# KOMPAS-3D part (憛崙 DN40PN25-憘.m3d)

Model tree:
1. Объединить компоненты:1  (labels: СЕНС DN40PN25)
2. Эскиз:1
3. Операция выдавливания:1
     Расстояние 1 = 14
4. Фаска:1
     Угол = 45; Длина 1 = 2; Длина 2 = 2

Referenced files in D:\Савин\!СЕНСОР\3D для заказчика\!Новый перечень\СЕНС\1. СЕНС\DN40\: СЕНС DN40PN25.a3d
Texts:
  СЕНС DN40PN25-СВ
  ООО НПП Сенсор
  СЕНС DN40PN25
